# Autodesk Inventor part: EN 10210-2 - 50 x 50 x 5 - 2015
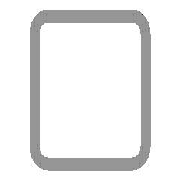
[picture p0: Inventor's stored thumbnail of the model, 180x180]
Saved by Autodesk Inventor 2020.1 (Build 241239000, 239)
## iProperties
Created: 2019-01
Part Number: EN 10210-2 - 50 x 50 x 5 - 2015
Material: Stahl, weich
Description: Rohrleitung
Document SubType Name: Modeling
Standard: DIN
Designer: lutzd
Standard Revision: 2006-07
Standards Organization: DIN
Language: de-DE
Size Designation: 50 x 50 x 5
Categories: <MemberInstance><Categories><Category DisplayName="Profile" InternalName="089c4875-fa83-4c05-b084-43b9cc11f5ed" Mnemonic="GRDR"><CategoryParameter DisplayName="
Stock Number: 50 x 50 x 5
Mass: 13811.7 g
Surface Area: 6839.04 cm^2
Volume: 1759.45 cm^3
Density: 7.85 g/cm^3
Appearance: Halbpoliert
IsCustomPart: 1
G_W: 50,000 mm
G_H: 50,000 mm
Dimensions: 50x50x2015 mm
Mass: 13,812 kg
DocNumber: ADSK-014210
Folder: .
+CF8A1589-21CF-466C-852D-167CA8DA44A4+SCHNITTDETAIL1: Schnittwinkel 90,00 grd
+A54445F7-5321-42E2-AC98-364175EDB9BD+SCHNITTDETAIL2: Schnittwinkel 90,00 grd
G_L: 2015,000 mm
_CCFamilyMember: 16
_CCFamilyDisplayName: DIN EN 10210-2 (USAS B17.1 quadratisch) - Rohrleitung — In Klammern angegebene Größen wurden aufgehoben
_FrameMemberDoc: Frame Member File
_Version: 15.0.0
_GetPNFromCC: 1
Title: Profil-Bauteil
Author: lutzd
Revision Number: -
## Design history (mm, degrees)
node "Startebene"
node "Endebene"
sketch "Skizze"
  geometry: L1 (-25, -17.5)-(-25, 17.5); L2 (-17.5, 25)-(17.5, 25); L3 (25, 17.5)-(25, -17.5); L4 (17.5, -25)-(-17.5, -25); L5 (-15, 20)-(15, 20); L6 (20, 15)-(20, -15); L7 (15, -20)-(-15, -20); L8 (-20, -15)-(-20, 15); L9 (0, 37.175)-(0, -37.175) reference; L10 (-37.175, 0)-(37.175, 0) reference; A1 r 7.5 centre (-17.5, -17.5) between (-25, -17.5) and (-17.5, -25); A2 r 7.5 centre (-17.5, 17.5) between (-17.5, 25) and (-25, 17.5); A3 r 7.5 centre (17.5, 17.5) between (25, 17.5) and (17.5, 25); A4 r 7.5 centre (17.5, -17.5) between (17.5, -25) and (25, -17.5); A5 r 5 centre (-15, -15) between (-20, -15) and (-15, -20); A6 r 5 centre (-15, 15) between (-15, 20) and (-20, 15); A7 r 5 centre (15, 15) between (20, 15) and (15, 20); A8 r 5 centre (15, -15) between (15, -20) and (20, -15)
  constraints: 16 end point, 16 point on circle, 16 tangent, 8 centre point, 6 equal radius, 4 parallel, 2 perpendicular, 2 other
  dimensions: "d7" = 7.5 radius of A1 (= G_IR); "d10" = 50 distance between parallel lines of L2 L4 (= G_H); "d11" = 50 distance between parallel lines of L1 L3 (= G_W); "d12" = 5 distance between parallel lines of L3 L6 (= G_T); "d15" = 25 distance between parallel lines of L2 L10 (= 0.5 x d10); "d16" = 25 distance between parallel lines of L9 L3 (= 0.5 x d11); "d19" = 5 radius of A5 (= G_T); "d20" = 5 distance between parallel lines of L4 L7 (= G_T)
extrude "Körper" new body sketch "Skizze" stored distance "d3" = 2015 (= G_L); taper "d4" = 0 deg
node "Driven Length"
  sketch "Sketch3"
    geometry: L1 (0, 0)-(10, 0) reference
    constraints: 2 end point, 1 horizontal
  workplane "Work Plane3"
  sketch "Sketch4"
    geometry: L1 (-2, 25)-(12, 25) reference; L2 (-2, 2040)-(12, 2040) reference
    dimensions: "d18" = 2015 distance between parallel lines of L1 L2 (derived)
workplane "Arbeitsebene4"
feature "Trennen1"
workplane "Arbeitsebene5"
feature "Trennen2"
body "Solid1"
other parameters: "G_W" = 50 [user parameter; used in 1 equation term], "G_H" = 50 [user parameter; used in 1 equation term], "G_T" = 5 [user parameter; used in 3 equation terms], "G_IR" = 7.5 [user parameter; used in 1 equation term], "G_L" = 2015 (= d18) [user parameter; used in 1 equation term], "G_OFFSET_START" = -25 [user parameter; used in 1 equation term], "d13" = 25 (= -G_OFFSET_START), "d17" = 90 deg
